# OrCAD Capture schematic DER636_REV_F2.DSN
size C; title: DER-636 RevF2; rev: F2
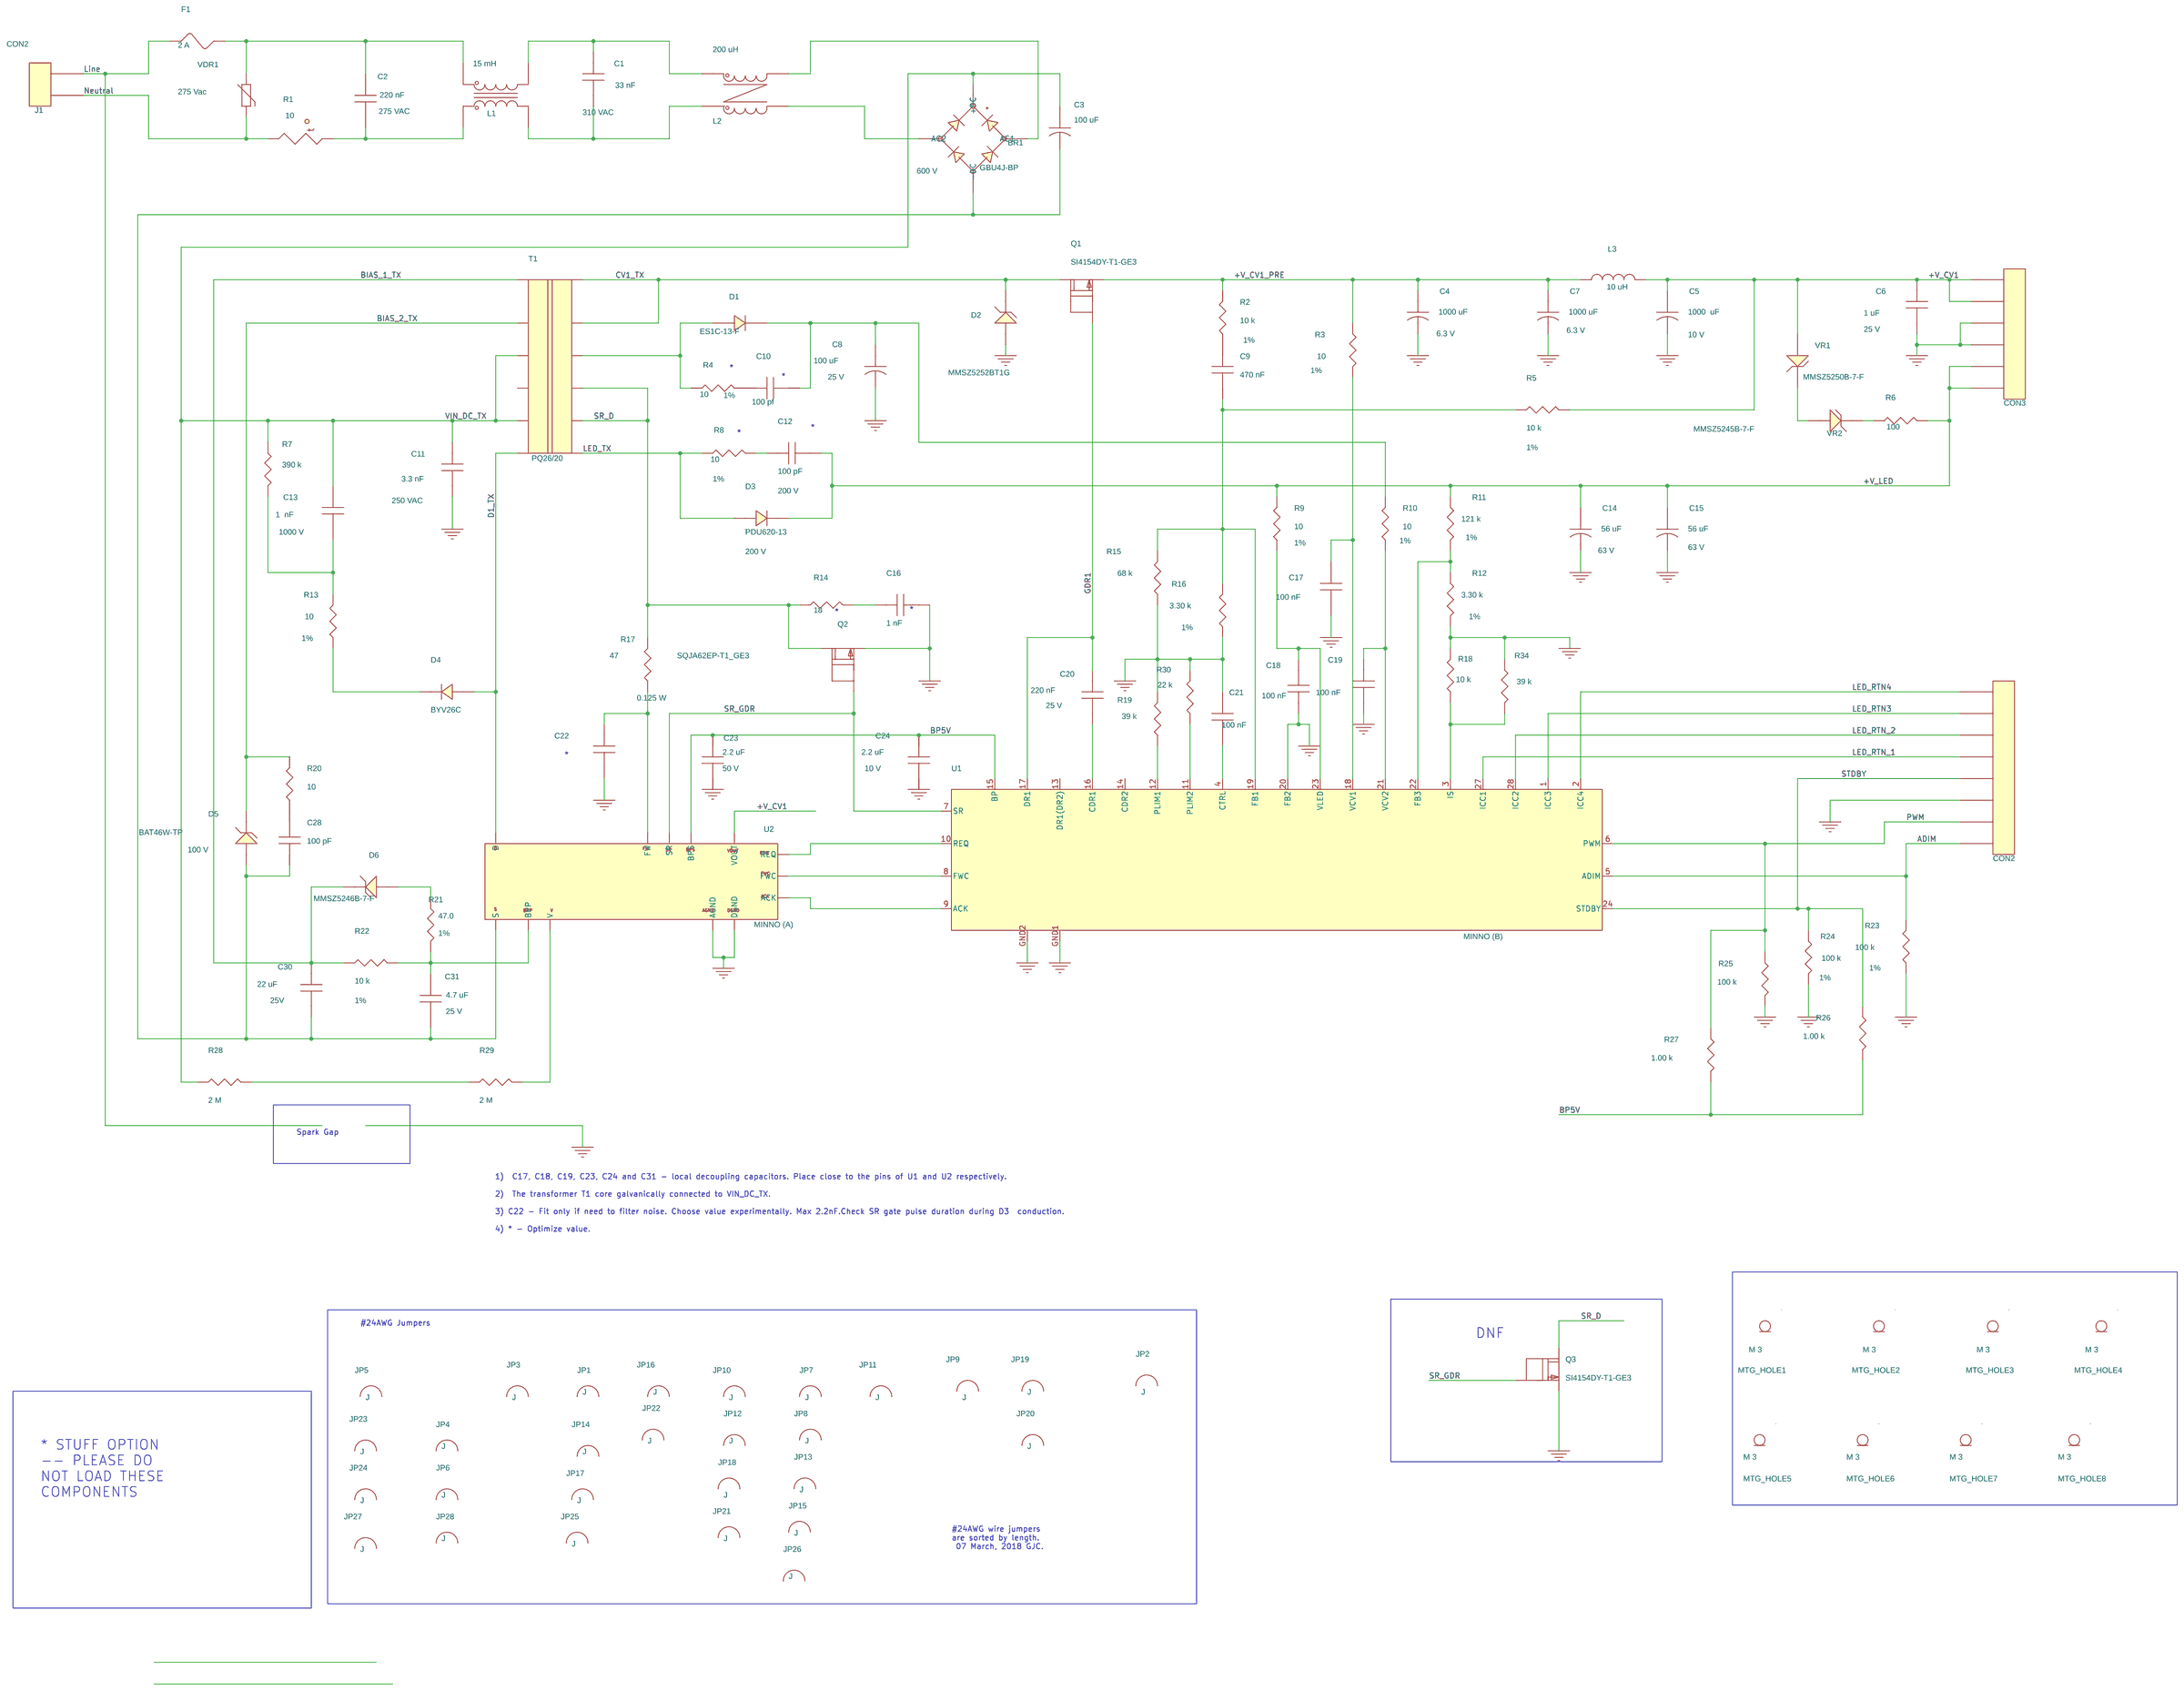
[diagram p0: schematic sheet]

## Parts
BR1  GBU4J-BP  [pidaxbridgegbu8]
C1  33 nF  [pi_np_cap400x160ls300d040]
C2  220 nF  [pi_np_710x315ls590d040]
C3  100 uF  [pipolcapclyd630ls300040]
C4  1000 uF  [pipolcapclyd320ls140030]
C5  1000  uF  [pipolcapclyd320ls140030]
C6  1 uF  [pismc0805]
C7  1000 uF  [pipolcapclyd320ls140030]
C8  100 uF  [pipolcapcyld250ls100030]
C9  470 nF  [pismc0805]
C10  100 pf  [pismc0805]
C11  3.3 nF  [pinpycaprad540x290ls400040]
C12  100 pF  [pismc0805]
C13  1  nF  [pismc1206]
C14  56 uF  [pipolcapcyld400ls200040]
C15  56 uF  [pipolcapcyld400ls200040]
C16  1 nF  [pismc0805]
C17  100 nF  [pismc0805]
C18  100 nF  [pismc1210]
C19  100 nF  [pismc0805]
C20  220 nF  [pismc0805]
C21  100 nF  [pismc0805]
C22  2.2 nF  [pismc0805]
C23  2.2 uF  [pinpcaprad200x100200030]
C24  2.2 uF  [pismc0805]
C28  100 pF  [pismc0805]
C30  22 uF  [pismc1206]
C31  4.7 uF  [pismc0805]
CON2  TERMINAL BLOCK  [pi_trmblk_5p08_8pin_H]
CON3  TERMINAL BLOCK  [pi_trmblk_5p08_6pin_H]
D1  ES1C-13-F  [pismdo214ac12]
D2  MMSZ5252BT1G  [pi_sm_sod-123_12]
D3  PDU620-13  [pismdpowerdi5]
D4  BYV26C  [pidv200x150x040sod57]
D5  BAT46W-TP  [pi_sm_sod-123_12]
D6  MMSZ5246B-7-F  [pi_sm_sod-123_12]
F1  2 A  [pi_tr5_submin_fuse]
J1  CON2  [pi_hdr_2pin_phoenix_ls295]
JP1  J  [pi_jumper500]
JP2  J  [pi_jumper1900]
JP3  J  [pi_jumper400]
JP4  J  [pi_jumper300]
JP5  J  [pi_jumper200]
JP6  J  [pi_jumper300]
JP7  J  [pi_jumper800]
JP8  J  [pi_jumper800]
JP9  J  [pi_jumper1100]
JP10  J  [pi_jumper700]
JP11  J  [pi_jumper900]
JP12  J  [pi_jumper700]
JP13  J  [pi_jumper800]
JP14  J  [pi_jumper500]
JP15  J  [pi_jumper800]
JP16  J  [pi_jumper600]
JP17  J  [pi_jumper500]
JP18  J  [pi_jumper700]
JP19  J  [pi_jumper1200]
JP20  J  [pi_jumper1200]
JP21  J  [pi_jumper700]
JP22  J  [pi_jumper600]
JP23  J  [pi_jumper200]
JP24  J  [pi_jumper200]
JP25  J  [pi_jumper500]
JP26  J  [pi_jumper800]
JP27  J  [pi_jumper200]
JP28  J  [pi_jumper300]
L1  15 mH  [piind4p944x650ls492x394060]
L2  200 uH  [pi_coil_2]
L3  10 uH  [pi_choke_H625xD539ls290d046]
MTG_HOLE1  M 3  [pimtgholem3]
MTG_HOLE2  M 3  [pimtgholem3]
MTG_HOLE3  M 3  [pimtgholem3]
MTG_HOLE4  M 3  [pimtgholem3]
MTG_HOLE5  M 3  [pimtgholem3]
MTG_HOLE6  M 3  [pimtgholem3]
MTG_HOLE7  M 3  [pimtgholem3]
MTG_HOLE8  M 3  [pimtgholem3]
Q1  SI4154DY-T1-GE3  [PI_SM_SOT669]
Q2  SQJA62EP-T1_GE3  [pismpqfn5x6b]
Q3  SI4154DY-T1-GE3  [PI_SM_SOT669]
R1  10  [pirad400x175ls250031]
R2  10 k  [pismr0805]
R3  10  [pismr0805]
R4  10  [pismr0805]
R5  10 k  [pismr0805]
R6  100  [pismr0805]
R7  390 k  [pismr1206]
R8  10  [pismr0805]
R9  10  [pismr0805]
R10  10  [pismr0805]
R11  121 k  [pismr0805]
R12  3.30 k  [pismr0805]
R13  10  [pismr1206]
R14  18  [pismr1206]
R15  68 k  [pismr0805]
R16  3.30 k  [pismr0805]
R17  47  [pi18wresd080ls400d030]
R18  10 k  [pismr0805]
R19  39 k  [pismr0805]
R20  10  [pismr0805]
R21  47.0  [pismr0805]
R22  10 k  [pismr0805]
R23  100 k  [pismr0805]
R24  100 k  [pismr0805]
R25  100 k  [pismr0805]
R26  1.00 k  [pismr0805]
R27  1.00 k  [pismr0805]
R28  2 M  [pismr0805]
R29  2 M  [pismr0805]
R30  22 k  [pismr0805]
R34  39 k  [pismr0805]
T1  PQ26/20  [pi_bobbin_bpq26_20_12p]
U1  MINNO (B)  [pi_sm_HSOP28_ALT]
U2  MINNO (A)  [pi_ic_insop_24d_IPC]
VDR1  275 Vac  [pidisc500x225ls335x140040]
VR1  MMSZ5250B-7-F  [pi_sm_sod-123_12]
VR2  MMSZ5245B-7-F  [pi_sm_sod-123_12]

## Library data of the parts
BR1 = DISCRETE_BRIDGE_+~~-: Disp_Voltage: 600 V; Part Number: 15-00721-00
C1 = CAP_NP: Disp_Voltage: 310 VAC; Part Number: 20-01114-00; Voltage: 310 VAC
C2 = CAP_NP: Disp_Voltage: 275 VAC; Part Number: 20-00900-00; Voltage: 275 VAC
C3 = CAP_POL: ALT_SYMBOLS: pipolcapd630ls3000401600lhoriz; Disp_Voltage: 400 V; FPLIST: pipolcapclyd630ls300040,pipolcapd630ls3000401600lhoriz; Part Number: 20-00491-00; Voltage: 400 V
C4 C7 = CAP_POL: Disp_Voltage: 6.3 V; Part Number: 20-09113-00; Voltage: 6.3 V
C5 = CAP_POL: ALT_SYMBOLS: pipolcapclyd320ls140d30h750; Disp_Voltage: 10 V; FPLIST: pipolcapclyd320ls140030,pipolcapclyd320ls140d30h750; Part Number: 20-00005-00; Voltage: 10 V
C6 = CAP_NP: Disp_Voltage: 25 V; Part Number: 20-00923-00; Voltage: 25 V
C8 = CAP_POL: ALT_SYMBOLS: pipolcapcyld250ls100030h; Disp_Voltage: 25 V; FPLIST: pipolcapcyld250ls100030,pipolcapcyld250ls100030h; Part Number: 20-00432-00; Voltage: 25 V
C9 = CAP_NP: Disp_Voltage: 50 V; Part Number: 20-00896-00; Voltage: 50 V
C10 = CAP_NP: Disp_Voltage: 100 V; Part Number: 24-00030-00; Voltage: 100 V
C11 = CAP_NP: ALT_SYMBOLS: pinpycaprad540x290ls400040h; Disp_Voltage: 250 VAC; FPLIST: pinpycaprad540x290ls400040,pinpycaprad540x290ls400040h; Part Number: 20-00377-00; Voltage: 250 VAC
C12 C28 = CAP_NP: Disp_Voltage: 200 V; Part Number: 20-00760-00; Voltage: 200 V
C13 = CAP_NP: Disp_Voltage: 1000 V; Part Number: 20-01131-00; Voltage: 1000 V
C14 C15 = CAP_POL: ALT_SYMBOLS: pipolcapcyld10ls514HD040H; Disp_Voltage: 63 V; FPLIST: pipolcapcyld400ls200040,pipolcapcyld10ls514HD040H; Part Number: 20-09077-00; Voltage: 63 V
C16 = CAP_NP: ALT_SYMBOLS: pismc0805_1; Disp_Voltage: 200 V; FPLIST: pismc0805,pismc0805_1; Part Number: 20-00737-00; Voltage: 200 V
C17 C19 C21 = CAP_NP: Disp_Voltage: 25 V; Part Number: 20-08599-00; Voltage: 25 V
C18 = CAP_NP: Disp_Voltage: 200 V; Part Number: 20-00940-00; Voltage: 200 V
C20 = CAP_NP: Disp_Voltage: 25 V; Part Number: 20-00237-00; Voltage: 25 V
C22 = CAP_NP: Disp_Voltage: 50 V; Part Number: 20-00961-00; Voltage: 50 V
C23 = CAP_NP: Disp_Voltage: 50 V; Part Number: 20-01082-00; Voltage: 50 V
C24 = CAP_NP: Disp_Voltage: 10 V; Part Number: 20-08747-00; Voltage: 10 V
C30 = CAP_NP: Disp_Voltage: 25V; Part Number: 20-08945-00; Voltage: 25 V
C31 = CAP_NP: Disp_Voltage: 25 V; Part Number: 20-09137-00; Voltage: 16 V
CON2 = CON8: Part Number: 35-00445-00
CON3 = CON6: Part Number: 35-00419-00
D1 = DIODE: Part Number: 15-00352-00
D2 = DIODE_ZENER: Part Number: 15-01099-00
D3 = DIODE_PD5: Disp_Voltage: 200 V; Part Number: 15-01257-00
D4 = DIODE: ALT_SYMBOLS: pidax425x150040sod57; FPLIST: pidv200x150x040sod57,pidax425x150040sod57; Part Number: 15-00128-00
D5 = DIODE_ZENER: Disp_Voltage: 100 V; Part Number: 15-01049-00
D6 = DIODE_ZENER: Part Number: 15-01092-00
F1 = FUSE: Part Number: 40-00002-00
J1 = CON2: Part Number: 35-00321-00
JP1 JP14 JP17 JP25 = JUMPER_1: Part Number: 65-00122-00
JP2 = JUMPER_1: Part Number: 65-00136-00
JP3 = JUMPER_1: Part Number: 65-00121-00
JP4 JP6 JP28 = JUMPER_1: Part Number: 65-00120-00
JP5 JP23 JP24 JP27 = JUMPER_1: Part Number: 65-00119-00
JP7 JP8 JP13 JP15 JP26 = JUMPER_1: Part Number: 65-00125-00
JP9 = JUMPER_1: Part Number: 65-00128-00
JP10 JP12 JP18 JP21 = JUMPER_1: Part Number: 65-00124-00
JP11 = JUMPER_1: Part Number: 65-00126-00
JP16 JP22 = JUMPER_1: Part Number: 65-00123-00
JP19 JP20 = JUMPER_1: Part Number: 65-00129-00
L1 = INDUCTOR_4P_revD: Part Number: 30-00416-00
L2 = TORRID_4P_14_23: Part Number: 32-00316-00
L3 = INDUCTOR: Part Number: 30-00460-00
MTG_HOLE1-MTG_HOLE8 = MTG_HOLE_M3: Part Number: 66-00005-00
Q1 Q3 = FET_N_SGD_123_4_5: ALT_SYMBOLS: pismso8; FPLIST: PI_SM_SOT669,pismso8; Part Number: 50-00257-00
Q2 = FET_N_SGD_123_4_5678: Part Number: 50-00273-00
R1 = THERMISTOR: ALT_SYMBOLS: pirad400x175ls250040_h; FPLIST: pirad400x175ls250031,pirad400x175ls250040_h; Part Number: 90-00013-00
R2 R5 R18 R22 = R: Disp_Tol: 1%; Part Number: 05-00684-00
R3 R4 R8-R10 R20 = R: Disp_Tol: 1%; Part Number: 05-00492-00
R6 = R: Part Number: 05-01495-00
R7 = R: Part Number: 05-01414-00
R11 = R: Disp_Tol: 1%; Part Number: 05-00788-00
R12 R16 = R: Disp_Tol: 1%; Part Number: 05-05369-00
R13 = R: Disp_Tol: 1%; Part Number: 05-00001-00
R14 = R: Part Number: 05-01310-00
R15 = R: Part Number: 05-01563-00
R17 = R: ALT_SYMBOLS: pi18wresd080ls300d030,pi18wresd080ls400d030; Disp_Power: 0.125 W; FPLIST: pi18wvresd80ls100d030,pi18wresd080ls300d030,pi18wresd080ls400d030; Part Number: 05-02305-00
R19 R34 = R: Part Number: 05-01557-00
R21 = R: Disp_Tol: 1%; Part Number: 05-03476-00
R23 R24 = R: Disp_Tol: 1%; Part Number: 05-00780-00
R25 = R: Part Number: 05-01567-00
R26 R27 = R: Disp_Tol: 1%; Part Number: 05-03310-00
R28 R29 = R: Disp_Tol: 5%; Part Number: 05-05595-00
R30 = R: Part Number: 05-01551-00
T1 = BPQ26_20_12P_GENERIC: Part Number: 25-00025-00
U1 = MINNO_Master_HSOP: Part Number: 10-01061-00
U2 = MinnoPriSec: ALT_SYMBOLS: pi_ic_insop_24d; FPLIST: pi_ic_insop_24d_IPC, pi_ic_insop_24d; Part Number: 10-01060-00
VDR1 = VARISTOR: Part Number: 85-00014-00
VR1 = DIODE_ZENER: Part Number: 15-01093-00
VR2 = DIODE_ZENER: Part Number: 15-01091-00

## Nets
GND POWER: C4.2 C5.2 C6.2 C7.2 C8.2 C11.2 C14.2 C15.2 C16.2 C17.2 C18.1 C19.2 C21.1 C22.2 C23.2 C24.2 CON2.3 CON3.3 CON3.4 D2.2 Q2.1(S) Q3.1(S) R12.2 R15.2 R16.2 R18.1 R19.1 R23.2 R24.2 R25.1 R30.1 R34.1 U1.20(FB2) U1.GND1 U1.GND2 U2.2(DGND) U2.3(AGND)
VIN_DC_TX: BR1.1(+DC) C3.1 C11.1 C13.1 R7.1 R28.1 T1.3 T1.5
+V_CV1: C5.1 C6.1 CON3.5 CON3.6 L3.2 R5.2 U2.8(VOUT) VR1.2
+V_CV1_PRE: C4.1 C7.1 L3.1 Q1.1(S) R2.2 R3.2
+V_LED: C12.2 C14.1 C15.1 CON3.1 CON3.2 D3.2(C) R6.2 R9.2 R11.1
ADIM: CON2.1 R23.1 U1.5(ADIM)
BIAS_1_TX: C30.1 D6.1 R22.1 T1.1
BIAS_2_TX: D5.1 R20.2 T1.2
BP5V: C23.1 C24.1 R26.1 R27.1 U1.15(BP) U2.6(BPS)
CV1_TX: D2.1 Q1.5(D) T1.11 T1.12
D1_TX: D4.2 T1.6 U2.24(D)
GDR1: C20.1 Q1.4(G) U1.17(DR1)
LED_RTN3: CON2.7 U1.1(ICC3)
LED_RTN4: CON2.8 U1.2(ICC4)
LED_RTN_1: CON2.5 U1.27(ICC1)
LED_RTN_2: CON2.6 U1.28(ICC2)
LED_TX: D3.1(A1) R8.1 T1.7
Line: F1.1 J1.2
Neutral: J1.1 R1.1 VDR1.2
PWM: CON2.2 R25.2 R27.2 U1.6(PWM)
SR_D: Q2.5(D) Q3.5(D) R14.1 R17.1 T1.8 T1.9
SR_GDR: Q2.4(G) Q3.4(G) U1.7(SR) U2.7(SR)
STDBY: CON2.4 R24.1 R26.2 U1.24(STDBY)
N264690: C2.1 F1.2 L1.1 VDR1.1
N264850: C1.1 L1.2 L2.1
N264859: C1.2 L1.3 L2.2
N264880: BR1.2(AC1) L2.4
N265348: C13.2 R7.2 R13.1
N265875: C31.1 R21.2 R22.2 U2.14(BPP)
N265882: D6.2 R21.1
N266083: BR1.4(-DC) C3.2 C28.1 C30.2 C31.2 D5.2 U2.16(S)
N266812: R29.2 U2.13(V)
N268528: U1.8(FWC) U2.5(FWC)
N268540: U1.9(ACK) U2.4(ACK)
N268853: C12.1 R8.2
N269394: R11.2 R12.1 U1.22(FB3)
N270162: C9.2 R5.1 R15.1 R16.1 U1.19(FB1)
N270954: C21.2 U1.4(CTRL)
N271382: R19.2 U1.12(PLIM1)
N276717: C20.2 U1.16(CDR1)
N282191: D1.2 R4.1 T1.10
N282590: C22.1 R17.2 U2.9(FW)
N283932: C8.1 C10.2 D1.1 R10.2
N291571: U1.10(REQ) U2.1(REQ)
N311390: R28.2 R29.1
N348677: D4.1 R13.2
N374143: C16.1 R14.2
N467521: C2.2 L1.4 R1.2
N471745: C19.1 R10.1 U1.21(VCV2)
N472207: C17.1 R3.1 U1.18(VCV1)
N535301: C18.2 R9.1 U1.23(VLED)
N551504: BR1.3(AC2) L2.3
N563936: VR1.1 VR2.2
N600270: R30.2 U1.11(PLIM2)
N606979: R18.2 R34.2 U1.3(IS)
N615359: R6.1 VR2.1
N640125: C10.1 R4.2
N640126: C28.2 R20.1
N640127: C9.1 R2.1

Not connected (* = marked no-connect by the designer): D3 3(A3); JP1 1 2; JP2 1 2; JP3 1 2; JP4 1 2; JP5 1 2; JP6 1 2; JP7 1 2; JP8 1 2; JP9 1 2; JP10 1 2; JP11 1 2; JP12 1 2; JP13 1 2; JP14 1 2; JP15 1 2; JP16 1 2; JP17 1 2; JP18 1 2; JP19 1 2; JP20 1 2; JP21 1 2; JP22 1 2; JP23 1 2; JP24 1 2; JP25 1 2; JP26 1 2; JP27 1 2; JP28 1 2; MTG_HOLE1 1; MTG_HOLE2 1; MTG_HOLE3 1; MTG_HOLE4 1; MTG_HOLE5 1; MTG_HOLE6 1; MTG_HOLE7 1; MTG_HOLE8 1; Q1 2(S2) 3(S3); Q2 2(S2) 3(S3) 6(D6) 7(D7) 8(D8); Q3 2(S2) 3(S3); T1 4; U1 13(DR1(DR2)) 14(CDR2)

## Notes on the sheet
- *
- *
- *
- *
- *
- *
- *
- Spark Gap
- 1)  C17, C18, C19, C23, C24 and C31 - local decoupling capacitors. Place close to the pins of U1 and U2 respectively.
  2)  The transformer T1 core galvanically connected to VIN_DC_TX.
  3) C22 - Fit only if need to filter noise. Choose value experimentally. Max 2.2nF.Check SR gate pulse duration during D3  conduction.
  4) * - Optimize value.
- #24AWG Jumpers
- DNF
- * STUFF OPTION
  -- PLEASE DO
  NOT LOAD THESE
  COMPONENTS
- #24AWG wire jumpers
  are sorted by length.
   07 March, 2018 GJC.
